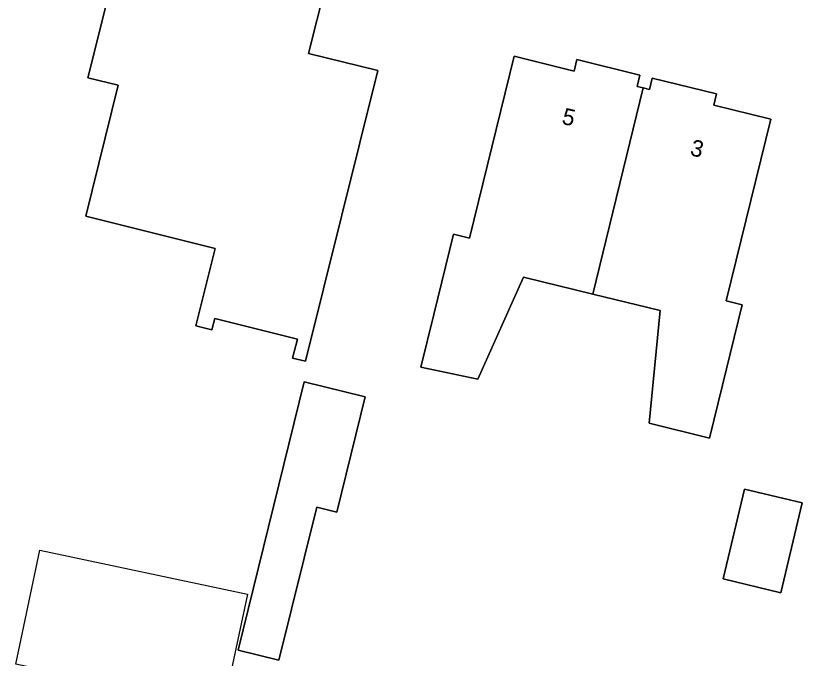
# Model space of a CAD drawing. Extents: x 161139 to 161601, y 381708 to 382245.
# Drawn here: x 161482.2 to 161529.75, y 382109.71 to 382148.58 of the extents above; entities that cross this region are included whole.
import ezdxf

# ---------------------------------------------------------------- set-up
doc = ezdxf.new("R2010")
doc.units = 0
for name, color, linetype in [('IMGEO_Erf', 7, 'Continuous'), ('IMGEO_Pand', 7, 'Continuous'), ('IMGEO_Pand_nummerreeks', 7, 'Continuous'), ('IMGEO_Pand_vergunning_verleend', 7, 'Continuous')]:
    doc.layers.add(name, color=color, linetype=linetype)

msp = doc.modelspace()

# ---------------------------------------------------------------- linework, layer by layer
at = {"layer": 'IMGEO_Erf'}
for points in [[(161486.566, 382144.832), (161488.704, 382153.431), (161489.861, 382153.143), (161489.575, 382151.995), (161496.23, 382150.338), (161496.516, 382151.486), (161500.917, 382150.389), (161499.897, 382146.301), (161504.087, 382145.265), (161499.715, 382127.678), (161498.939, 382127.871), (161499.224, 382129.017), (161494.228, 382130.258), (161494.056, 382129.569), (161493.086, 382129.811), (161494.252, 382134.504), (161486.428, 382136.449), (161488.398, 382144.376)], [(161512.324, 382146.126), (161515.951, 382145.235), (161516.121, 382145.928), (161519.93, 382144.992), (161519.762, 382144.307), (161520.139, 382144.214), (161520.515, 382144.122), (161520.683, 382144.806), (161524.565, 382143.853), (161524.397, 382143.169), (161527.844, 382142.322), (161525.15, 382131.328), (161526.122, 382131.09), (161524.932, 382126.234), (161524.147, 382123.029), (161520.5, 382123.927), (161521.155, 382130.743), (161517.083, 382131.744), (161512.894, 382132.773), (161510.135, 382126.59), (161506.686, 382127.32), (161507.469, 382130.515), (161508.659, 382135.371), (161509.63, 382135.132)], [(161499.638, 382126.427), (161503.333, 382125.516), (161501.615, 382118.549), (161500.393, 382118.85), (161498.111, 382109.598), (161495.638, 382110.208)], [(161529.748, 382119.108), (161528.458, 382113.678), (161524.957, 382114.51), (161526.247, 382119.94)]]:
    msp.add_lwpolyline(points, close=True, dxfattribs=at)
at = {"layer": 'IMGEO_Pand'}
for points in [[(161504.087, 382145.265), (161499.897, 382146.301), (161500.917, 382150.389), (161496.516, 382151.486), (161496.23, 382150.338), (161489.575, 382151.995), (161489.861, 382153.143), (161488.704, 382153.431), (161486.566, 382144.832), (161488.398, 382144.376), (161486.428, 382136.449), (161494.252, 382134.504), (161493.086, 382129.811), (161494.056, 382129.569), (161494.228, 382130.258), (161499.224, 382129.017), (161498.939, 382127.871), (161499.715, 382127.678)], [(161517.083, 382131.744), (161520.139, 382144.214), (161519.762, 382144.307), (161519.93, 382144.992), (161516.121, 382145.928), (161515.951, 382145.235), (161512.324, 382146.126), (161509.63, 382135.132), (161508.659, 382135.371), (161507.469, 382130.515), (161506.686, 382127.32), (161510.135, 382126.59), (161512.894, 382132.773)], [(161517.083, 382131.744), (161521.155, 382130.743), (161520.5, 382123.927), (161524.147, 382123.029), (161524.932, 382126.234), (161526.122, 382131.09), (161525.15, 382131.328), (161527.844, 382142.322), (161524.397, 382143.169), (161524.565, 382143.853), (161520.683, 382144.806), (161520.515, 382144.122), (161520.139, 382144.214)], [(161495.638, 382110.208), (161498.111, 382109.598), (161500.393, 382118.85), (161501.615, 382118.549), (161503.333, 382125.516), (161499.638, 382126.427)], [(161529.748, 382119.108), (161526.247, 382119.94), (161524.957, 382114.51), (161528.458, 382113.678)]]:
    msp.add_lwpolyline(points, close=True, dxfattribs=at)
at = {"layer": 'IMGEO_Pand_vergunning_verleend'}
msp.add_lwpolyline([(161496.204, 382113.578), (161494.74, 382106.686), (161482.199, 382109.349), (161483.663, 382116.241)], close=True, dxfattribs=at)

# ---------------------------------------------------------------- texts
at = {"layer": 'IMGEO_Pand_nummerreeks'}
for s, p in [('5', (161515.157, 382142.055)), ('3', (161522.917, 382140.153))]:
    msp.add_text(s, height=1, rotation=346.2281, dxfattribs=at).set_placement(p)

doc.saveas('drawing.dxf')
